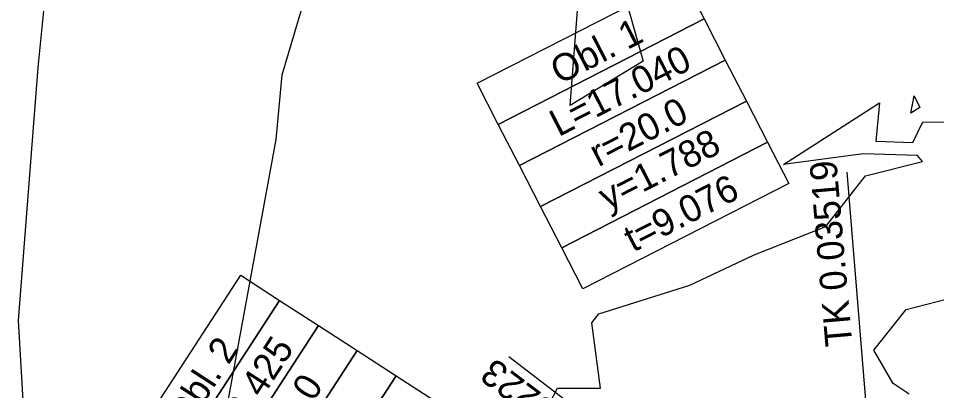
# Model space of a CAD drawing. Extents: x -549394 to -546608, y -1037055 to -1033629.
# Drawn here: x -547651 to -547531.9, y -1035097.3 to -1035049 of the extents above; entities that cross this region are included whole.
import ezdxf

# ---------------------------------------------------------------- set-up
doc = ezdxf.new("R2010")
doc.units = 0
for name, color, linetype in [('hlavni_vrst', 7, 'Continuous'), ('norm_vrst', 7, 'Continuous'), ('x_popis_oblouky_C1', 7, 'Continuous')]:
    doc.layers.add(name, color=color, linetype=linetype)

msp = doc.modelspace()

# ---------------------------------------------------------------- linework, layer by layer
at = {"layer": 'hlavni_vrst'}
for p, q in [((-547648.39, -1035055.39), (-547647.45, -1035045.8)), ((-547650.97, -1035088.23), (-547648.39, -1035055.39)), ((-547650.05, -1035103.66), (-547650.97, -1035088.23))]:
    msp.add_line(p, q, dxfattribs=at)
at = {"layer": 'norm_vrst'}
for p, q in [((-547574.2, -1035039.51), (-547569.97, -1035054.57)), ((-547579.44, -1035060.31), (-547577.91, -1035040.91)), ((-547616.75, -1035056.34), (-547614.3, -1035048.04)), ((-547569.97, -1035054.57), (-547579.44, -1035060.31)), ((-547617.56, -1035064.71), (-547616.75, -1035056.34)), ((-547551.78, -1035067.99), (-547539.33, -1035059.97)), ((-547539.33, -1035059.97), (-547539.8, -1035064.93)), ((-547535.26, -1035061.32), (-547534.84, -1035059.05)), ((-547534.84, -1035059.05), (-547534.1, -1035060.59)), ((-547534.1, -1035060.59), (-547535.26, -1035061.32)), ((-547535.01, -1035065.1), (-547533.68, -1035062.42)), ((-547533.68, -1035062.42), (-547529.79, -1035062.46)), ((-547624.56, -1035103.1), (-547617.56, -1035064.71)), ((-547539.8, -1035064.93), (-547535.01, -1035065.1)), ((-547541.44, -1035066.59), (-547551.78, -1035067.99)), ((-547534.39, -1035066.81), (-547541.44, -1035066.59)), ((-547533.73, -1035067.58), (-547534.39, -1035066.81)), ((-547541.11, -1035069.46), (-547533.73, -1035067.58)), ((-547546.28, -1035076.04), (-547541.11, -1035069.46)), ((-547555.56, -1035079.72), (-547546.28, -1035076.04)), ((-547563.91, -1035083.64), (-547555.56, -1035079.72)), ((-547575.71, -1035087.34), (-547563.91, -1035083.64)), ((-547535.88, -1035086.78), (-547527.84, -1035084.74)), ((-547576.61, -1035088.51), (-547575.71, -1035087.34)), ((-547540.04, -1035092.08), (-547535.88, -1035086.78)), ((-547575.48, -1035097), (-547576.61, -1035088.51)), ((-547537.54, -1035096.4), (-547540.04, -1035092.08)), ((-547535.49, -1035097.8), (-547537.54, -1035096.4)), ((-547593.1, -1035119.88), (-547581.07, -1035097.02)), ((-547581.07, -1035097.02), (-547575.48, -1035097))]:
    msp.add_line(p, q, dxfattribs=at)
at = {"layer": 'x_popis_oblouky_C1'}
for points in [[(-547591.48, -1035057.43), (-547564.79, -1035043.73), (-547562.05, -1035049.07), (-547588.74, -1035062.77)], [(-547588.74, -1035062.77), (-547562.05, -1035049.07), (-547559.31, -1035054.41), (-547586, -1035068.1)], [(-547586, -1035068.1), (-547559.31, -1035054.41), (-547556.57, -1035059.75), (-547583.26, -1035073.44)], [(-547583.26, -1035073.44), (-547556.57, -1035059.75), (-547553.83, -1035065.09), (-547580.52, -1035078.78)], [(-547580.52, -1035078.78), (-547553.83, -1035065.09), (-547551.09, -1035070.43), (-547577.78, -1035084.12)], [(-547638.46, -1035107.52), (-547622.14, -1035082.34), (-547617.1, -1035085.61), (-547633.42, -1035110.78)], [(-547633.42, -1035110.78), (-547617.1, -1035085.61), (-547612.07, -1035088.87), (-547628.39, -1035114.04)], [(-547628.39, -1035114.04), (-547612.07, -1035088.87), (-547607.03, -1035092.14), (-547623.36, -1035117.31)], [(-547623.36, -1035117.31), (-547607.03, -1035092.14), (-547602, -1035095.4), (-547618.32, -1035120.57)], [(-547618.32, -1035120.57), (-547602, -1035095.4), (-547596.97, -1035098.67), (-547613.29, -1035123.84)]]:
    msp.add_lwpolyline(points, close=True, dxfattribs=at)
for points in [[(-547540.13, -1035110.2), (-547543.5, -1035068.97)], [(-547554.59, -1035118.19), (-547587.38, -1035092.96)]]:
    msp.add_lwpolyline(points, dxfattribs=at)

# ---------------------------------------------------------------- texts
for s, rotation, p in [('Obl. 1', 27.1802, (-547580.8, -1035057.63)), ('L=17.040', 27.1802, (-547580.91, -1035064.43)), ('r=20.0', 27.1802, (-547575.76, -1035068.34)), ('y=1.788', 27.1802, (-547574.57, -1035073.98)), ('TK 0.03519', 94.9843, (-547542.82, -1035091.43)), ('t=9.076', 27.1802, (-547571.26, -1035079.42)), ('Obl. 2', 57.0619, (-547629.1, -1035102.37)), ('L=19.425', 57.0619, (-547625.81, -1035108.32)), ('KT 0.05223', 142.971, (-547569.93, -1035107.56)), ('r=300.0', 57.0619, (-547620.03, -1035110.12))]:
    msp.add_text(s, height=3.5, rotation=rotation, dxfattribs=at).set_placement(p)

doc.saveas('drawing.dxf')
